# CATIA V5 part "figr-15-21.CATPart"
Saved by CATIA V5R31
Part number: Part1
Bounding box of the stored display mesh (mm): x -81.56 to 85.56, y -36.965 to 25.965, z 0 to 42
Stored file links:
  D:\PROJECTS\Project 2021\US EDITION\CATIA V5 6R 2021\Resources\Part Files\c15_catia_v5_6r2021_prt\figr-15-21.CATPart
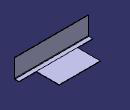
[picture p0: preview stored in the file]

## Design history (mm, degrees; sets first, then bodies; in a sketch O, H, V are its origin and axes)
SheetMetalParameters1: Thickness 1, BendRadius 1, KFactor 0.325257 {= log(min(100,max(20*SheetMetalParameters1.BendRadius,SheetMetalParameters1.Thickness)/SheetMetalParameters1.Thickness))/log(100)/2}, ReliefRadialLength 1, ReliefAxialLength 2, MinimumBendRadius 0
Body1 (main body)
  Sketch1 on xy-plane, origin (0, 0, 0), H (1, 0, 0), V (0, 1, 0)
    line L1 (-46.5596, 25.9646) -> (46.5596, 25.9646)
    line L2 (46.5596, 25.9646) -> (46.5596, -25.9646)
    line L3 (46.5596, -25.9646) -> (-46.5596, -25.9646)
    line L4 (-46.5596, -25.9646) -> (-46.5596, 25.9646)
    horizontal: L1 H, L3 H
    vertical: L2 V, L4 V
    symmetry: L1 L3 H, L4 L2 V
  Wall1: Thickness 1, Profile Sketch1
  d_NewWallOnEdge1: NewWallOnEdge_Edge edge [face of Wall1 | face of Wall1], NewWallOnEdge_Length 42, NewWallOnEdge_HeightLimitOffset 0, NewWallOnEdge_WidthOffset1 39, NewWallOnEdge_WidthOffset2 35, NewWallOnEdge_Angle 90, NewWallOnEdge_BendRadiusValue 1 {= SheetMetalParameters1.BendRadius}, NewWallOnEdge_BendTable SheetMetalParameters1, KFacteur 0.325257 {= log(min(100,max(20*d_NewWallOnEdge1.Radius,SheetMetalParameters1.Thickness)/SheetMetalParameters1.Thickness))/log(100)/2}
